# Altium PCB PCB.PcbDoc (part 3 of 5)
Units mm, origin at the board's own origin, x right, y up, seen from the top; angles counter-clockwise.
Board outline 101.6 x 53.34 mm, 6 copper layers (Top Layer, Int1 (GND), Int2, Int3, Int4 (GND), Bottom Layer), stack 1.625 mm thick; 228 components, 228 nets, 1016 pads, 995 vias.
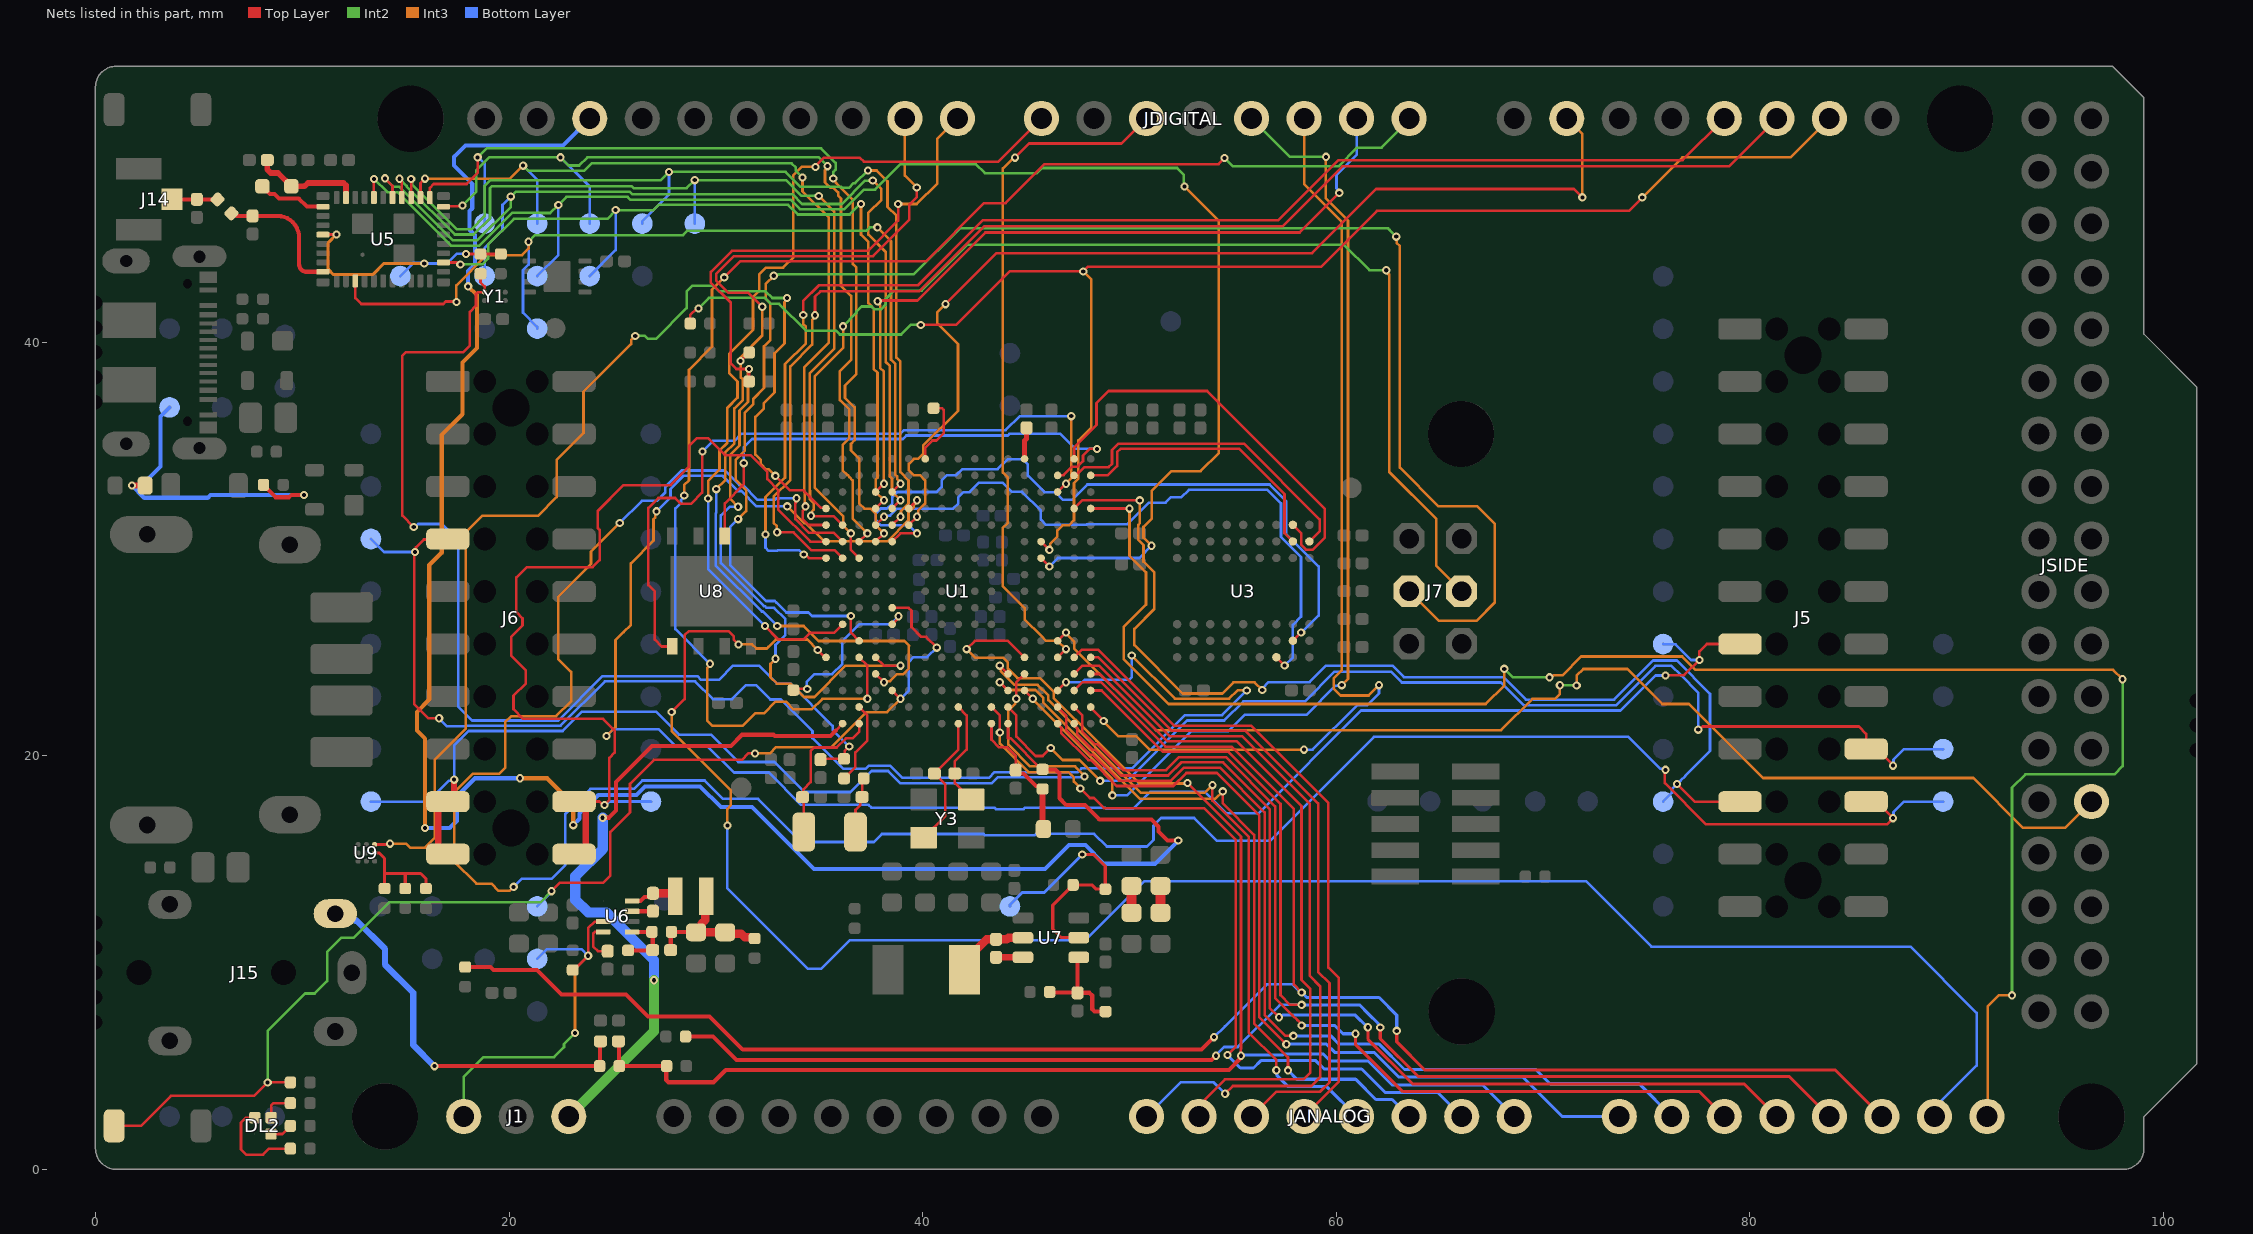
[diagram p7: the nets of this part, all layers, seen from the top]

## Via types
v1: diameter 0.4, hole 0.2, Top Layer to Bottom Layer, tented both sides, 995 vias

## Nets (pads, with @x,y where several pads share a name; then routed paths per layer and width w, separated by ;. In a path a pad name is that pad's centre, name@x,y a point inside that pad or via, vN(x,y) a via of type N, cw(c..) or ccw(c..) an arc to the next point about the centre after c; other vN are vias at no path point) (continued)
LEFT: JANALOG.22 R25.1 U1.T3 | length 97.2
  Top Layer w0.127: U1.T3@47.326,23.153 47.726,23.553 48.615,23.553 51.732,20.436 54.943,20.436 57.946,17.433 57.946,8.933 v1(58.326,8.553)
  Top Layer w0.15: v1(62.924,6.696) 62.924,6.163 64.291,4.796 84.142,4.796 JANALOG.22@86.386,2.553
  Top Layer w0.2: R25.1@17.878,9.784 19.103,9.784 19.243,9.644 21.343,9.644 22.528,8.459 25.653,8.459 26.722,7.39 29.697,7.39 31.297,5.79 53.49,5.79 v1(54.09,6.39)
  Bottom Layer w0.127: v1(54.09,6.39) 54.611,6.911 56.644,8.943 57.888,8.943 58.278,8.553 v1(58.326,8.553)
  Bottom Layer w0.15: v1(58.326,8.553) 58.575,8.305 62.075,8.305 62.924,7.455 v1(62.924,6.696)
M_7: C4.1 J15.2 R22.2 | length 19
  Top Layer w0.2: v1@16.389,4.989 24.371,4.989 R22.2@24.376,4.994 ; R22.2@24.38,4.99 24.4,5.01 24.4,6.17 C4.1@24.42,6.19
  Bottom Layer w0.3: J15.2@11.6,12.363 12.247,12.363 12.588,12.022 12.635,12.022 14,10.657 14,9.9 15.367,8.533 15.367,6.01 v1(16.389,4.988)
MEMS_32.768kHz: C72.1 R6.2 R9.1 Y1.2 | length 50.5
  Top Layer w0.127: v1(15.39,31.059) 14.843,31.606 14.843,39.348 14.999,39.505 17.763,39.505 18.1,39.841 18.1,41.461 18.4,41.761 18.4,42.318 18.497,42.415 Y1.2@18.819,42.415 18.819,42.692 18.619,42.892 R9.1@18.619,43.31 ; C72.1@35.065,19.805 35.104,19.844 35.646,19.844 35.649,19.847 36.097,19.847 36.225,19.975 36.225,20.225 v1(36.45,20.45)
  Bottom Layer w0.127: v1(15.39,31.059) 15.457,31.059 15.601,31.203 16.75,31.203 17.541,30.411 17.541,22.374 18.212,21.704 22.382,21.704 24.524,23.846 29.103,23.846 29.278,23.67 30.141,23.67 30.823,24.352 32.08,24.352 32.949,23.482 33.61,23.482 35.646,21.447 35.646,21.254 v1(36.45,20.45)
MIC: C4.2 JANALOG.16 R22.1 R23.2 U1.N5 | length 78.3
  Top Layer w0.127: v1(42.126,25.153) 42.53,25.557 44.122,25.557 U1.N5@44.922,24.757 ; v1(52.812,18.677) 55.394,16.095 55.394,5.824 55.382,5.812 55.382,5.497 v1(55.39,5.49)
  Top Layer w0.2: C4.2@25.29,6.19 25.31,6.17 25.31,5.01 R22.1@25.33,4.99 27.532,4.99 27.6,4.921 27.6,4.326 27.717,4.209 29.878,4.209 30.478,4.809 54.809,4.809 55.371,5.371 v1@55.371,5.471
  Top Layer w0.3: v1@55.371,5.471 v1(55.39,5.49)
  Int3 w0.127: v1(42.126,25.153) 42.536,24.743 43.888,24.743 44.117,24.515 44.117,24.21 44.574,23.753 45.679,23.753 46.332,23.099 46.332,22.795 48.403,20.724 50.474,18.653 52.788,18.653 v1(52.812,18.677)
  Bottom Layer w0.15: v1(55.39,5.49) 55.43,5.53 57.415,5.53 57.457,5.573 59.374,5.573 59.707,5.239 61.54,5.239 62.702,4.077 67.081,4.077 JANALOG.16@68.606,2.553
Net3V3_EN_X: 3V3_EN.X J1.1 R30.2 U6.3 | length 18.2
  Top Layer w0.127: R30.2@23.178,9.679 v1(23.825,10.326) 23.825,10.662 23.825,11.658 24.146,11.979 U6.3@24.621,11.979
  Int2 w0.127: J1.1@17.806,2.553 17.806,4.457 18.772,5.423 22.172,5.423 22.655,5.906 22.655,6.054 v1(23.19,6.59)
  Int3 w0.127: v1(23.19,6.59) 23.19,9.691 v1(23.825,10.326)
  Bottom Layer w0.127: 3V3_EN.X@21.362,10.173 21.83,10.641 23.51,10.641 v1(23.825,10.326)
Net5V_EN_X: 5V_EN.X R35.2 R36.1 U7.2 | length 12.7
  Top Layer w0.15: U7.2@47.55,11.2 46.706,11.2 46.289,11.616 46.289,12.767 R36.1@47.275,13.753 48.181,13.753 48.387,13.547 R35.2@48.831,13.547 48.831,14.669 48.274,15.226 v1(47.718,15.226)
  Bottom Layer w0.15: 5V_EN.X@44.222,12.713 44.222,12.793 44.805,13.377 45.869,13.377 v1(47.718,15.226)
NetC20_1: C20.1 U7.6 | length 1.3
  Top Layer w0.3: C20.1@43.55,10.25 U7.6@44.85,10.25
NetC20_2: C20.2 L1.1 U7.5 | length 3.7
  Top Layer w0.4: L1.1@42.016,9.653 42.016,10.103 42.566,10.653 42.619,10.653 43.086,11.12 44.069,11.12 44.149,11.2 U7.5@44.85,11.2
NetC35_2: C35.2 U1.N17 | length 1.5
  Top Layer w0.25: U1.N17@44.926,34.353 44.926,35.227 45.026,35.327 C35.2@45.026,35.853
NetC36_2: C36.2 L4.2 R7.2 U1.L1 | length 6.6
  Top Layer w0.127: U1.L1@43.326,21.553 43.326,20.778 43.698,20.407 44.093,20.407 44.5,20 C36.2@44.5,19.3 ; L4.2@45.778,16.454 L4.2@45.8,16.476
  Top Layer w0.2: C36.2@44.5,19.3 44.658,19.142 44.883,19.142 45.485,18.54 45.65,18.54 R7.2@45.8,18.39
  Top Layer w0.3: L4.2@45.8,16.476 R7.2@45.8,18.39
NetC38_1: C38.1 R14.1 U5.41 | length 6.6
  Top Layer w0.2: R14.1@6.572,46.228 ccw(c6.881,46.538) 6.881,46.1 C38.1@7.6,46.1 8.807,46.1 cw(c8.807,45.06) 9.847,45.06 9.847,43.76 ccw(c10.207,43.76) 10.207,43.4 U5.41@11,43.4
NetC39_1: C39.1 J14.SIG R14.2 | length 2.2
  Top Layer w0.2: J14.SIG@3.731,46.932 ccw(c3.731,46.904) J14.SIG@3.703,46.904 C39.1@4.903,46.904 5.102,46.906 ccw(c5.129,47.104) 5.128,46.904 5.896,46.904 R14.2@5.9,46.9
NetC42_1: C42.1 L2.2 U5.31 | length 5.3
  Top Layer w0.28: C42.1@8.308,48.804 8.308,48.347 8.475,48.18 8.827,48.18 L2.2@9.475,47.532 10.107,47.532 10.271,47.696 11.999,47.696 12.115,47.58 U5.31@12.115,46.99
NetC43_1: C43.1 L3.1 U6.8 | length 2.3
  Top Layer w0.2: U6.8@25.871,12.979 26.359,12.979 26.547,13.168 26.726,13.168 C43.1@26.907,13.349
  Top Layer w0.4: C43.1@26.907,13.349 27.84,13.349 L3.1@27.988,13.201
NetC43_2: C43.2 U6.7 | length 1
  Top Layer w0.2: U6.7@25.871,12.479 C43.2@26.907,12.479
NetC47_1: C47.1 R15.1 R16.2 U6.5 | length 3.1
  Top Layer w0.2: R16.2@25.758,10.586 26.934,10.586 C47.1@26.947,10.599 26.947,11.439 R15.1@26.907,11.479 U6.5@25.871,11.479
NetC47_2: C47.2 C48.2 C49.2 L3.2 R15.2 R39.1 | length 7
  Top Layer w0.2: C47.2@27.817,10.599 27.817,11.439 R15.2@27.857,11.479 29.028,11.479 C49.2@29.045,11.462
  Top Layer w0.4: C49.2@29.045,11.462 C49.2@29.083,11.462 ; L3.2@29.488,13.201 29.488,12.053 29.317,11.882 29.317,11.695 C49.2@29.083,11.462 ; R39.1@31.874,11.162 31.819,11.217 31.399,11.217 31.222,11.394 30.519,11.394 C48.2@30.451,11.462 C49.2@29.083,11.462
NetC50_2: C50.2 U6.4 | length 2
  Top Layer w0.127: U6.4@24.621,11.479 24.154,11.479 24.079,11.404 24.079,10.758 24.292,10.546 C50.2@24.768,10.546
NetC51_1: C51.1 R8.1 Y2.2 | length 2.8
  Top Layer w0.127: Y2.2@36.75,16.31 36.75,17.378 36.982,17.61 36.982,17.912 C51.1@37.07,18 37.07,18.82 R8.1@37.15,18.9
NetC52_1: C52.1 U1.J2 Y3.3 | length 5.2
  Top Layer w0.127: U1.J2@41.726,22.353 42.126,21.953 42.126,20.302 41.556,19.732 C52.1@41.556,19.143 41.556,18.679 Y3.3@42.35,17.885
NetC53_1: C53.1 U1.C1 Y2.1 | length 7.2
  Top Layer w0.127: C53.1@34.195,18 34.25,17.945 Y2.1@34.25,16.31 ; C53.1@34.23,18 34.23,18.366 34.584,18.72 34.584,20.227 34.755,20.397 35.845,20.397 36.288,20.841 36.612,20.841 36.926,21.155 U1.C1@36.926,21.553
NetC54_1: C54.1 U1.J1 Y3.1 | length 6.7
  Top Layer w0.127: Y3.1@40.05,16.035 41.1,17.085 41.1,18.604 C54.1@40.561,19.143 41.726,20.308 U1.J1@41.726,21.553
NetC60_1: C60.1 C61.2 | length 1.3
  Top Layer w0.5: C60.1@51.5,12.403 C61.2@51.5,13.703
NetC65_1: C65.1 R31.2 R33.2 U7.1 | length 5.2
  Top Layer w0.2: R31.2@46.155,8.588 R31.2@46.142,8.575 46.162,8.555 47.472,8.555 C65.1@47.492,8.535 ; U7.1@47.55,10.25 47.492,10.192 C65.1@47.492,8.535 ; R33.2@48.842,7.625 48.317,7.625 48.2,7.742 48.2,8.4 48.065,8.535 C65.1@47.492,8.535
NetC68_1: C68.1 C69.2 | length 1.3
  Top Layer w0.5: C68.1@50.1,12.403 C69.2@50.1,13.703
NetDL1_C: DL1.C PWR_LED.X R10.2 | length 16.3
  Top Layer w0.2: R10.2@8.125,33.085 8.71,32.5 9.362,32.5 9.472,32.61 v1(10.086,32.61)
  Top Layer w0.3: v1(1.767,33.062) DL1.C@2.4,33.062
  Bottom Layer w0.2: PWR_LED.X@3.582,36.843 3.146,36.407 3.146,33.98 2.227,33.062 v1(1.767,33.062) 2.355,32.473 5.431,32.473 5.569,32.61 v1(10.086,32.61)
NetDL2_1: DL2.1 R12.1 | length 1.1
  Top Layer w0.15: DL2.1@8.495,1.705 9.045,1.705 R12.1@9.425,2.085
NetDL2_2: DL2.2 R13.1 | length 1.6
  Top Layer w0.127: DL2.2@8.495,2.495 8.495,3.095 8.6,3.2 R13.1@9.425,3.2
NetDL2_3: DL2.3 R11.1 | length 4.7
  Top Layer w0.127: DL2.3@7.705,2.495 7.273,2.495 7.037,2.259 7.037,0.963 7.29,0.71 8.11,0.71 8.4,1 R11.1@9.425,1
NetJ1_3: J1.3 U1.B1 | length 33.1
  Top Layer w0.127: 35.799,21.22 35.799,21.225 U1.B1@36.122,21.549
  Top Layer w0.2: v1(24.525,17) 24.527,17.002 24.825,17.002 25.166,17.343 25.166,18.728 26.913,20.475 30.733,20.475 31.271,21.013 32.79,21.013 32.845,20.959 35.537,20.959 35.799,21.22
  Int2 w0.5: J1.3@22.886,2.553 27.009,6.676 v1(27.009,9.139)
  Bottom Layer w0.5: v1(24.525,17) 24.525,15.486 23.207,14.167 23.207,13.037 23.823,12.421 24.705,12.421 27.009,10.116 v1(27.009,9.139)
NetJDIGITAL_3: JDIGITAL.3 R7.1 U1.M1 | length 97.4
  Top Layer w0.127: U1.M1@44.126,21.553 44.126,20.851 44.239,20.851 R7.1@45.75,19.34
  Top Layer w0.2: R7.1@45.75,19.34 46.414,19.34 46.611,19.143 46.611,17.943 46.942,17.613 47.842,17.613 48.542,16.913 51.063,16.913 51.412,16.564 51.412,16.327 51.841,15.898 52.36,15.898 v1(52.362,15.897)
  Int3 w0.2: v1(15.932,16.5) 15.932,20.823 15.542,21.213 15.542,22.113 16.142,22.713 16.142,29.213 16.742,29.813 16.742,35.513 17.742,36.513 17.742,39.013 18.442,39.713 18.442,42.276 v1(18.021,42.696) ; v1(20.529,18.91) 21.844,18.91 23.101,17.653 v1(23.101,16.64)
  Bottom Layer w0.2: v1(15.932,16.5) 17.129,16.5 17.471,16.842 17.471,18.032 18.349,18.91 v1(20.529,18.91) ; v1(18.021,42.696) 18.021,43.432 18.349,43.76 18.349,45.177 18.095,45.432 18.095,46.346 18.221,46.473 18.221,47.648 17.334,48.535 17.334,48.961 17.886,49.513 22.602,49.513 JDIGITAL.3@23.902,50.813 ; v1(23.101,16.64) 23.41,16.949 23.41,17.202 24.315,18.107 26.162,18.107 26.568,18.513 29.242,18.513 30.242,17.513 31.742,17.513 34.742,14.513 45.913,14.513 47.077,15.677 47.871,15.677 48.775,14.773 51.238,14.773 v1(52.362,15.897)
NetL2_1: L2.1 U5.34 | length 3.3
  Top Layer w0.2: L2.1@8.075,47.532 8.447,47.16 8.652,47.16 8.867,46.946 9.827,46.946 10.222,46.55 U5.34@11,46.55
NetLPO_IN_X: LPO_IN.X R9.2 R40.2 U5.37 | length 12.8
  Top Layer w0.127: v1(17.922,44.265) 17.925,44.263 18.616,44.263 R9.2@18.619,44.26 R40.2@19.6,44.26
  Top Layer w0.15: U5.37@11,45.2 v1(11.65,45.2)
  Int3 w0.15: v1(11.65,45.2) 11.248,44.798 11.248,43.56 11.273,43.535 11.273,43.496 11.508,43.26 13.4,43.26 13.94,43.8 v1(15.9,43.8)
  Bottom Layer w0.127: LPO_IN.X@14.742,43.193 15.382,43.833 15.867,43.833 v1(15.9,43.8) 15.909,43.791 15.917,43.8 17,43.8 17.465,44.265 v1(17.922,44.265)
NetR3_2: R3.2 U1.E7 | length 7.9
  Top Layer w0.127: R3.2@33.776,23.146 33.858,23.229 v1(34.416,23.229) ; U1.E7@38.526,26.353 38.779,26.606 38.779,26.688 v1(38.831,26.741)
  Bottom Layer w0.127: v1(34.416,23.229) 34.399,23.245 34.399,23.578 34.764,23.943 35.617,23.943 36.117,24.444 36.117,25.544 36.926,26.353 38.444,26.353 v1(38.831,26.741)
NetR5_2: R5.2 U1.G17 | length 3.4
  Top Layer w0.127: U1.G17@40.126,34.353 40.126,34.905 40.464,35.243 40.669,35.243 41.011,35.586 41.011,36.726 40.935,36.803 R5.2@40.526,36.803
NetR6_1: R6.1 R8.2 U1.C2 | length 4.1
  Top Layer w0.127: R8.2@36.2,18.9 36.748,19.448 36.748,20.158 37.326,20.737 37.326,21.953 U1.C2@36.926,22.353
NetR32_2: R32.2 R34.2 R37.2 U9.C2 | length 5.4
  Top Layer w0.15: U9.C2@13.5,15.3 13.507,15.293 13.725,15.293 13.98,15.038 13.98,14.307 ; R37.2@13.98,13.575 13.98,14.307 ; R34.2@14.98,13.575 14.98,14.307 ; R32.2@15.98,13.575 15.98,14.051 15.724,14.307 14.98,14.307 ; 13.98,14.307 14.98,14.307
PA0_C: JANALOG.20 U1.T1 | length 48.6
  Top Layer w0.127: U1.T1@47.326,21.553 47.326,21.494 47.472,21.348 47.472,21.296 47.472,21.046 48.224,20.294 48.343,20.294 49.595,19.043 51.873,19.043 52.505,19.674 54.527,19.674 56.793,17.408 56.793,7.786 v1(57.226,7.353)
  Top Layer w0.15: v1(61.527,6.866) 61.527,6.296 63.701,4.123 79.735,4.123 JANALOG.20@81.306,2.553
  Bottom Layer w0.15: v1(57.226,7.353) 57.294,7.353 57.396,7.455 60.924,7.455 61.513,6.866 v1(61.527,6.866)
PA1: J6.17 J6.19 POWER_EN.X U1.N4 | length 52.2
  Top Layer w0.127: v1(44.526,22.753) 44.526,23.553 U1.N4@44.922,23.949
  Top Layer w0.3: J6.19@17.042,15.239 16.926,15.239 16.574,15.591 16.574,17.427 16.926,17.779 17.342,17.779 17.342,18.839 v1(17.343,18.841)
  Int3 w0.127: v1(44.526,22.753) 44.474,22.701 44.474,22.511 44.141,22.178 44.141,20.537 45.195,19.482 47.368,19.482 47.831,19.02 v1(47.831,18.994)
  Bottom Layer w0.127: POWER_EN.X@13.322,17.779 16.072,17.779 17.09,18.796 17.299,18.796 v1(17.343,18.841) 17.343,20.499 18.04,21.196 22.593,21.196 23.524,22.127 27.108,22.127 28.22,21.015 29.763,21.015 31.085,19.692 32.83,19.692 34.278,18.245 36.512,18.245 37.528,19.26 38.329,19.26 38.915,18.674 43.346,18.674 43.625,18.953 47.79,18.953 v1(47.831,18.994)
PA1_C: JANALOG.19 U1.T2 | length 46.4
  Top Layer w0.127: U1.T2@47.326,22.353 47.726,21.953 47.726,21.151 48.329,20.548 48.448,20.548 49.7,19.297 51.768,19.297 52.399,19.928 54.673,19.928 57.047,17.554 57.047,8.28 57.883,7.443 57.888,7.443 58.117,7.215 58.117,7.21 58.326,7.001 v1(58.326,6.953)
  Top Layer w0.15: v1(60.926,6.553) 60.926,6.048 63.219,3.754 77.564,3.754 JANALOG.19@78.766,2.553
  Bottom Layer w0.15: v1(58.326,6.953) 59.929,6.953 60.329,6.553 v1(60.926,6.553)
PA2: JDIGITAL.15 U1.N3 | length 50.6
  Top Layer w0.127: U1.N3@44.926,23.153 v1(45.326,22.753)
  Int2 w0.127: JDIGITAL.15@55.906,50.813 57.759,48.96 v1(59.504,48.96)
  Int3 w0.127: v1(45.326,22.753) 45.326,22.723 49.173,18.876 v1(49.173,18.083) ; v1(59.504,48.96) 59.499,48.955 59.499,46.949 60.566,45.883 60.566,23.713 v1(60.266,23.413)
  Bottom Layer w0.127: v1(49.173,18.083) 49.891,18.083 53.004,21.196 54.792,21.196 55.574,21.978 58.553,21.978 59.966,23.39 60.243,23.39 v1(60.266,23.413)
PA3: JDIGITAL.16 U1.U2 | length 47.4
  Top Layer w0.127: U1.U2@48.126,22.353 48.126,22.328 48.751,21.703 v1(48.751,21.678)
  Int3 w0.127: v1(48.751,21.678) 48.751,21.652 49.457,20.946 50.316,20.946 50.969,20.293 v1(58.44,20.293) ; JDIGITAL.16@58.446,50.813 58.446,47.644 60.266,45.824 60.266,24.113 59.875,23.722 59.875,23.251 60.213,22.913 61.566,22.913 v1(62.066,23.413)
  Bottom Layer w0.127: v1(58.44,20.293) 58.849,20.293 60.992,22.437 61.486,22.437 62.066,23.017 v1(62.066,23.413)
PA4: JANALOG.21 R24.1 U1.U3 | length 81.4
  Top Layer w0.127: U1.U3@48.126,23.153 48.656,23.153 51.627,20.182 54.793,20.182 57.305,17.671 57.305,8.418 57.769,7.953 v1(58.326,7.953)
  Top Layer w0.15: v1(62.126,6.853) 62.126,6.32 63.957,4.488 81.91,4.488 JANALOG.21@83.846,2.553
  Top Layer w0.2: R24.1@28.535,6.419 29.868,6.419 30.997,5.29 53.966,5.29 v1@54.166,5.49
  Top Layer w0.3: v1@54.166,5.49 v1(54.19,5.49)
  Bottom Layer w0.127: v1(54.19,5.49) 54.19,5.531 54.574,5.915 55.236,5.915 57.274,7.953 v1(58.326,7.953)
  Bottom Layer w0.15: v1(58.326,7.953) 61.126,7.953 61.555,7.524 62.026,7.054 62.026,7.02 62.126,6.92 v1(62.126,6.853)
PA6: J6.7 PCLK.X U1.R3 | length 69.6
  Top Layer w0.127: v1(16.619,21.81) 16.095,21.81 15.413,22.492 15.413,29.813 15.502,29.902 15.502,30.079 15.876,30.452 J6.7@17.316,30.452 ; U1.R3@46.526,23.153 v1(46.926,23.553)
  Int3 w0.127: v1(50.11,24.842) 52.197,22.755 54.825,22.755 55.23,23.16 55.665,23.16 v1(55.672,23.153)
  Bottom Layer w0.127: PCLK.X@13.322,30.479 13.951,29.85 v1(15.45,29.85) ; v1(16.619,21.81) 16.619,21.808 17.007,21.42 17.904,21.42 17.934,21.45 22.487,21.45 24.629,23.592 28.997,23.592 29.854,22.735 30.789,22.735 31.463,23.409 31.945,23.409 32.634,22.72 33.151,22.72 34.675,21.196 34.675,20.851 36.152,19.374 37.251,19.374 37.396,19.519 38.429,19.519 39.021,18.928 43.198,18.928 43.477,19.207 47.492,19.207 47.669,19.385 50.115,19.385 52.688,21.958 54.477,21.958 v1(55.672,23.153) ; v1(46.926,23.553) 47.734,23.553 47.855,23.674 49.998,23.674 50.11,23.786 v1(50.11,24.842)
PA7: JDIGITAL.13 U1.R5 | length 33.5
  Top Layer w0.127: v1(44.461,48.919) 45.143,49.601 49.614,49.601 JDIGITAL.13@50.826,50.813 ; U1.R5@46.526,24.753 v1(46.926,25.153)
  Int3 w0.127: v1(44.461,48.919) 44.407,48.919 43.882,48.393 43.882,33.687 44.117,33.452 44.117,31.255 43.872,31.01 43.872,28.208 44.936,27.143 44.936,26.591 45.736,25.791 45.974,25.553 46.526,25.553 v1(46.926,25.153)
PA8: U1.E15 U5.3 UART7_RX.X | length 46.4
  Top Layer w0.127: U5.3@12.565,42.96 12.565,42.135 12.856,41.844 16.819,41.844 16.936,41.961 17.434,41.961 v1(17.453,41.943) ; U1.E15@38.526,32.753 v1(38.926,33.153)
  Int2 w0.127: v1(20.943,44.851) 21.265,45.173 28.415,45.173 28.63,45.388 37.284,45.388 37.444,45.548 v1(37.81,45.548)
  Int3 w0.127: v1(17.453,41.943) 17.453,42.749 18.907,44.204 20.63,44.204 20.943,44.516 v1(20.943,44.851) ; v1(37.81,45.548) 38.469,44.89 38.469,39.151 38.667,38.954 38.667,33.605 38.771,33.502 38.771,33.382 38.926,33.227 v1(38.926,33.153)
  Bottom Layer w0.127: v1(20.943,44.851) 20.943,43.751 20.671,43.479 20.671,41.427 21.362,40.737 UART7_RX.X@21.362,40.653
PA9: JDIGITAL.17 U1.D15 | length 38.1
  Top Layer w0.127: U1.D15@37.726,32.753 v1(38.126,33.153) ; v1(37.825,41.978) 37.856,42.009 39.742,42.009 43.033,45.3 58.227,45.3 v1(60.144,47.216)
  Int3 w0.127: v1(37.825,41.978) 37.825,41.904 37.944,41.785 37.944,38.751 38.126,38.568 v1(38.126,33.153)
  Bottom Layer w0.127: v1(60.144,47.216) 60.144,47.29 60.009,47.425 60.009,48.076 60.986,49.052 JDIGITAL.17@60.986,50.813
PA10: BLE_ON.X U1.D14 U5.14 | length 41.4
  Top Layer w0.127: U5.14@16.83,43.85 17.418,43.85 cw(c17.418,43.53) 17.483,43.843 cw(c17.418,43.53) v1(17.644,43.756) ; U1.D14@37.726,31.953 v1(38.126,32.353)
  Int2 w0.127: v1(17.644,43.756) 18.711,43.756 18.992,44.037 18.992,44.727 20.228,45.963 24.757,45.963 25.155,46.362 v1(25.155,46.386) 25.173,46.368 26.965,46.368 27.235,46.638 33.498,46.638 33.965,46.172 36.471,46.172 36.977,46.678 v1(37.016,46.678)
  Int3 w0.127: v1(37.016,46.678) 37.016,45.2 37.369,44.846 37.369,41.881 37.634,41.616 37.634,38.701 37.817,38.518 37.817,33.448 37.723,33.354 37.723,32.756 v1(38.126,32.353)
  Bottom Layer w0.127: BLE_ON.X@23.902,43.193 25.155,44.446 v1(25.155,46.386)
PA15: U1.A14 U9.C3 | length 55.1
  Top Layer w0.127: v1(32.878,33.532) 33.571,32.838 34.224,32.838 35.079,31.983 35.296,31.983 U1.A14@35.326,31.953
  Top Layer w0.15: U9.C3@13.5,15.7 14.194,15.7 v1(14.24,15.746)
  Int2 w0.127: v1(26.1,40.3) 26.566,40.3 26.707,40.159 27.099,40.159 28.583,41.644 28.583,42.436 28.877,42.729 29.871,42.729 30.142,42.458 32.408,42.458 32.733,42.133 v1(33.438,42.133)
  Int3 w0.127: v1(14.24,15.746) 15.024,15.746 15.217,15.553 15.933,15.553 16.4,16.02 16.4,19.8 17.9,21.3 17.9,30.8 18.7,31.6 21.4,31.6 22.3,32.5 22.3,34.3 23.6,35.6 23.6,37.6 25.9,39.9 25.9,40.1 v1(26.1,40.3) ; v1(32.878,33.532) 32.564,33.846 32.434,33.846 32.172,34.107 32.172,34.3 31.906,34.567 31.906,36.375 32.316,36.786 32.316,37.05 32.838,37.572 32.838,39.459 33.32,39.941 33.32,41.941 33.438,42.059 v1(33.438,42.133)
PB0: JANALOG.11 U1.U5 | length 32.1
  Top Layer w0.127: U1.U5@48.126,24.753 48.493,24.753 52.048,21.198 55.611,21.198 59.122,17.687 59.122,9.551 59.672,9 59.672,4.199 59.226,3.753 57.106,3.753 JANALOG.11@55.906,2.553
PB1: JANALOG.12 U1.T5 | length 31.6
  Top Layer w0.127: U1.T5@47.326,24.753 47.702,25.128 48.477,25.128 52.153,21.452 55.886,21.452 59.622,17.717 59.622,9.751 60.126,9.246 60.126,4.233 JANALOG.12@58.446,2.553
PB2: JSIDE.28 U1.R6 | length 57.8
  Top Layer w0.127: U1.R6@46.526,25.553 v1(46.926,25.953)
  Int2 w0.127: v1(70.812,23.408) 70.817,23.404 71.62,23.404 v1(71.625,23.399)
  Int3 w0.127: v1(46.926,25.953) 46.926,25.904 47.339,25.491 47.339,25.171 51.279,21.231 67.97,21.231 69.491,22.752 70.578,22.752 70.812,22.985 v1(70.812,23.408) ; v1(71.625,23.399) 71.625,23.868 71.95,24.193 74.076,24.193 75.77,22.499 77.055,22.499 80.635,18.919 90.805,18.919 93.215,16.509 95.25,16.509 JSIDE.28@96.52,17.779
PB3: J7.3 U1.C6 | length 80.8
  Top Layer w0.127: v1(36.526,26.753) 36.526,25.953 U1.C6@36.926,25.553
  Int2 w0.127: v1(32.802,43.208) 32.854,43.26 33.035,43.26 33.05,43.275 39.569,43.275 41.798,45.505 62.502,45.505 62.577,45.43 62.577,45.423 v1(62.9,45.1)
  Int3 w0.127: v1(31.076,31.438) 31.467,31.828 31.467,32.837 30.955,33.348 30.955,34.308 31.398,34.751 31.398,36.586 31.808,36.996 31.808,37.261 32.33,37.782 32.33,39.794 32.632,40.096 32.632,41.874 32.42,42.087 32.42,42.826 v1(32.802,43.208) ; v1(62.9,45.1) 62.918,45.082 62.918,44.8 63.072,44.646 63.072,33.936 64.954,32.054 66.827,32.054 67.664,31.216 67.664,27.396 66.797,26.529 64.949,26.529 J7.3@63.526,27.953
  Bottom Layer w0.127: v1(31.076,31.438) 30.69,31.052 30.69,29.224 32.433,27.482 32.846,27.482 32.921,27.407 32.924,27.407 33.407,26.924 34.48,26.924 34.651,26.753 v1(36.526,26.753)
PB4: JDIGITAL.11 U1.B7 | length 43.1
  Top Layer w0.127: v1(32.372,26.273) 33.017,25.628 34.247,25.628 34.563,25.943 35.717,25.943 U1.B7@36.126,26.353 ; v1@34.8,48.5 35.213,48.913 36.966,48.913 37.152,48.726 43.659,48.726 JDIGITAL.11@45.746,50.813
  Int3 w0.127: v1(29.626,32.438) 29.626,33.289 30.177,33.84 30.177,34.754 30.551,35.127 30.551,36.816 31.046,37.312 31.046,38.094 30.643,38.497 30.643,39.428 31.797,40.583 31.797,42.172 32.093,42.467 32.093,43.265 32.427,43.599 33.249,43.599 33.75,44.1 33.75,48.071 34.152,48.473 v1(34.822,48.473)
  Bottom Layer w0.127: v1(29.626,32.438) 29.626,29.018 v1(32.372,26.273)
PB5: JANALOG.23 U1.A5 | length 93.7
  Top Layer w0.127: v1(27.863,22.113) 28.495,22.745 28.495,25.828 28.692,26.025 30.608,26.025 30.871,25.762 30.871,25.601 v1(31.09,25.383) ; v1(34.926,25.113) 35.285,24.753 U1.A5@35.326,24.753
  Int3 w0.127: 27.863,21.913 27.863,21.19 30.719,18.333 30.719,17.595 30.559,17.434 v1(30.559,16.622) ; v1(31.09,25.383) 31.758,25.383 31.959,25.181 32.461,25.181 32.537,25.257 32.542,25.257 32.903,25.618 34.42,25.618 v1(34.926,25.113)
  Bottom Layer w0.127: v1(30.559,16.622) 30.559,13.587 34.455,9.691 35.094,9.691 36.487,11.084 47.881,11.084 50.727,13.931 72.083,13.931 75.244,10.77 87.764,10.77 90.969,7.565 90.969,5.021 88.926,2.978 JANALOG.23@88.926,2.553
PB7: JDIGITAL.18 U1.C5 | length 70.7
  Top Layer w0.127: v1(30.405,43.132) 31.176,43.903 40.157,43.903 42.973,46.72 44.013,46.72 45.9,48.606 54.306,48.606 v1(54.6,48.9) ; U1.C5@36.926,24.753 37.326,24.353 v1(37.326,22.753)
  Int2 w0.127: v1(54.6,48.9) 55,48.5 60.1,48.5 61,49.4 62.19,49.4 63.526,50.735 JDIGITAL.18@63.526,50.813
  Int3 w0.127: v1(28.468,32.583) 28.468,33.086 28.698,33.316 28.698,38.66 29.816,39.778 29.816,42.543 v1(30.405,43.132) ; v1(29.718,24.446) 29.718,24.372 29.592,24.245 29.592,21.688 29.823,21.456 31.304,21.456 31.9,22.052 32.325,22.052 32.886,22.614 33.386,22.614 33.756,22.243 34.636,22.243 35.146,22.753 v1(37.326,22.753)
  Bottom Layer w0.127: v1(28.468,32.583) 28.468,32.517 28.315,32.364 28.315,32.227 28.041,31.954 28.041,26.122 v1(29.718,24.446)
PB8: JDIGITAL.10 R29.1 U1.D5 | length 49.7
  Top Layer w0.127: R29.1@31.61,38.098 31.605,38.104 31.605,38.695 v1(31.6,38.7) 30.99,38.7 30.723,38.967 30.723,41.903 29.76,42.865 29.76,43.399 30.773,44.411 37.35,44.411 38.816,45.878 v1(38.816,46.678) ; U1.D5@37.726,24.753 38.126,24.353 v1(38.926,24.353)
  Int3 w0.127: v1(31.076,32.038) 30.701,32.413 30.701,34.559 31.144,35.002 31.144,36.691 31.554,37.102 31.554,38.654 v1(31.6,38.7) ; v1(32.885,24.689) 32.642,24.445 32.642,23.79 32.949,23.482 33.61,23.482 34.254,22.838 34.764,22.838 36.278,24.353 v1(38.926,24.353) ; v1(38.816,46.678) 39.709,46.678 40.709,47.678 40.709,49.84 JDIGITAL.10@41.682,50.813
  Bottom Layer w0.127: v1(31.076,32.038) 30.667,32.038 30.242,31.613 30.242,29.314 32.328,27.228 32.376,27.228 32.451,27.153 32.819,27.153 33.362,26.609 33.362,25.837 32.885,25.36 v1(32.885,24.689)
PB9: JDIGITAL.9 R28.1 U1.D4 | length 47
  Top Layer w0.127: v1(31.187,39.09) 31.202,39.09 R28.1@31.61,39.498 ; v1(32.242,41.713) 31.561,42.393 30.592,42.393 30.014,42.97 30.014,43.294 30.878,44.157 37.596,44.157 39.349,45.91 39.349,46.641 39.716,47.009 v1(39.716,47.478) ; U1.D4@37.726,23.953 v1(38.126,23.553)
  Int3 w0.127: v1(30.017,32.888) 30.447,33.318 30.447,34.664 30.89,35.107 30.89,36.796 31.3,37.207 31.3,38.199 31.21,38.29 31.21,39.275 32.242,40.307 v1(32.242,41.713) ; v1(32.972,26.273) 34.242,26.273 34.971,25.544 39.123,25.544 39.344,25.323 39.336,25.315 39.336,24.762 39.336,24.21 39.069,23.943 38.764,23.943 38.426,23.605 38.178,23.605 v1(38.126,23.553) ; JDIGITAL.9@39.142,50.813 39.142,48.052 v1(39.716,47.478)
  Bottom Layer w0.127: v1(30.017,32.888) 30.017,31.748 29.988,31.718 29.988,29.208 32.222,26.974 32.271,26.974 v1(32.972,26.273)
PB10: U1.P11 U5.28 WIFI_ON.X | length 74.9
  Top Layer w0.127: U5.28@13.465,46.99 v1(13.465,47.89) ; U1.P11@45.726,29.553 v1(46.126,29.153)
  Int2 w0.127: v1(13.465,47.89) 13.479,47.89 14.113,47.256 14.602,47.256 17.194,44.664 18.565,44.664 20.15,46.249 21.613,46.249 21.62,46.242 21.991,46.242 v1(22.382,46.633) 22.772,47.023 25.727,47.023 25.858,46.892 33.604,46.892 34.07,46.426 36.212,46.426 37.154,47.368 37.695,47.368 38.94,48.613 42.566,48.613 43.006,48.173 45.526,48.173 45.771,48.418 52.302,48.418 52.628,48.092 52.628,47.559 v1(52.663,47.524)
  Int3 w0.127: v1(51.071,30.153) 50.681,30.543 50.681,31.062 51.071,31.453 51.071,32.8 52.028,33.757 53.436,33.757 54.324,34.645 54.324,45.863 v1(52.663,47.524)
  Bottom Layer w0.127: WIFI_ON.X@21.362,43.193 22.382,44.213 v1(22.382,46.633) ; v1(46.126,29.153) 46.536,29.562 50.481,29.562 v1(51.071,30.153)
PB11: JDIGITAL.25 R19.1 U1.P12 | length 76.1
  Top Layer w0.127: R19.1@28.76,40.898 28.76,41.308 29.082,41.63 v1(29.156,41.63) ; v1(39.91,40.83) 41.622,40.83 44.209,43.417 v1(47.767,43.417) 48.002,43.652 59.28,43.652 61.973,46.344 74.144,46.344 v1(74.8,47) ; U1.P12@45.726,30.353 v1(46.126,29.953)
  Int2 w0.127: v1(29.156,41.63) 29.665,42.139 32.368,42.139 32.661,41.846 33.055,41.846 34.351,40.55 35.81,40.55 35.994,40.367 38.958,40.367 39.422,40.83 v1(39.91,40.83)
  Int3 w0.127: v1(46.126,29.953) 46.178,30.005 46.178,30.253 46.517,30.591 46.517,30.896 46.764,31.143 47.069,31.143 47.317,31.391 47.317,33.188 47.528,33.399 47.528,35.245 48.154,35.871 48.154,43.031 v1(47.767,43.417) ; v1(74.8,47) 76.732,48.932 81.965,48.932 JDIGITAL.25@83.846,50.813
PB12: J5.19 PB12.X U1.T14 | length 52.5
  Top Layer w0.127: U1.T14@47.326,31.953 47.726,32.353 50.496,32.353 v1(50.501,32.348) ; v1(76.482,18.633) 77.336,17.779 J5.19@79.525,17.779
  Int3 w0.127: v1(50.501,32.348) 50.501,31.242 50.427,31.168 50.427,30.438 50.681,30.184 50.681,29.383 51.204,28.86 51.204,27.106 50.236,26.138 50.236,25.341 52.568,23.009 54.491,23.009 55.032,23.55 56.044,23.55 v1(56.422,23.173)
  Bottom Layer w0.127: v1(56.422,23.173) 56.422,23.247 56.735,23.56 58.704,23.56 59.501,24.357 62.712,24.357 63.271,23.798 68.081,23.798 69.165,22.713 73.435,22.713 75.323,24.602 76.466,24.602 78.074,22.993 78.074,20.226 76.879,19.03 76.879,19.027 76.651,18.798 76.647,18.798 v1(76.482,18.633) 76.236,18.388 76.236,18.21 PB12.X@75.805,17.779
PB13: JANALOG.24 U1.U14 | length 88.1
  Top Layer w0.127: U1.U14@48.126,31.953 49.996,31.953 v1(50.001,31.948)
  Int2 w0.127: v1(68.125,24.199) 68.537,23.787 v1(70.316,23.787) ; v1(92.677,8.41) 92.677,18.451 93.325,19.099 97.625,19.099 98.025,19.499 v1(98.025,23.699)
  Int3 w0.127: v1(50.001,31.948) 50.001,29.662 50.8,28.863 50.8,27.307 49.719,26.226 49.719,24.68 51.899,22.501 67.227,22.501 68.125,23.399 v1(68.125,24.199) ; v1(70.316,23.787) 70.39,23.787 70.492,23.89 70.929,23.89 71.838,24.799 76.725,24.799 77.371,24.153 97.571,24.153 v1(98.025,23.699) ; JANALOG.24@91.466,2.553 91.499,2.586 91.499,7.873 92.036,8.41 v1(92.677,8.41)
PC0: JANALOG.15 U1.L2 | length 38.8
  Top Layer w0.127: U1.L2@43.326,22.353 43.732,21.947 v1(43.732,21.126) ; v1(47.625,18.418) 48.089,17.954 48.278,17.954 48.77,17.462 53.601,17.462 55.14,15.924 55.14,5.929 v1(54.736,5.525)
  Int3 w0.127: v1(43.732,21.126) 43.732,20.587 45.111,19.208 47.05,19.208 47.311,18.946 47.311,18.753 47.625,18.439 v1(47.625,18.418)
  Bottom Layer w0.15: v1(54.736,5.525) 55.36,4.9 56.001,4.9 56.354,5.253 59.017,5.253 59.419,4.85 61.229,4.85 62.36,3.719 64.899,3.719 JANALOG.15@66.066,2.553
PC1: DFSDM1_DATIN0.X J5.18 U1.M2 | length 54.9
  Top Layer w0.127: U1.M2@44.126,22.353 44.526,21.953 44.526,20.923 45.466,19.983 45.805,19.983 v1(46.192,20.37) ; v1(77.504,21.26) 77.56,21.26 77.715,21.415 85.269,21.415 85.625,21.059 J5.18@85.625,20.319 ; J5.18@86.145,20.319 v1@86.925,19.539
  Int3 w0.127: v1(46.192,20.37) 46.768,19.794 47.584,19.794 48.583,18.794 v1(48.583,18.784)
  Bottom Layer w0.127: v1(48.583,18.784) 49.873,18.784 52.793,21.704 54.582,21.704 55.507,22.629 58.486,22.629 59.923,24.066 62.644,24.066 63.171,23.538 67.969,23.538 69.07,22.437 73.517,22.437 75.428,24.348 76.208,24.348 76.66,23.896 77.504,23.052 v1(77.504,21.26) ; v1(86.925,19.519) 86.946,19.54 86.946,19.819 87.446,20.319 DFSDM1_DATIN0.X@89.345,20.319 DFSDM1_DATIN0.X@89.327,20.3
PC2: JANALOG.14 U1.M3 | length 35.5
  Top Layer w0.127: v1(43.726,23.553) U1.M3@44.126,23.153 ; v1(54.512,18.277) 54.512,17.695 56.031,16.177 56.031,7.047 57.666,5.411 v1(57.666,4.784)
  Int3 w0.127: v1(43.726,23.553) 44.104,23.175 45.456,23.175 45.824,22.807 45.824,22.584 50.489,17.92 54.155,17.92 v1(54.512,18.277)
  Bottom Layer w0.15: v1(57.666,4.784) 58.097,4.353 60.937,4.353 61.914,3.376 62.702,3.376 JANALOG.14@63.526,2.553
PC2_C: JANALOG.17 U1.R1 | length 41.4
  Top Layer w0.127: U1.R1@46.526,21.553 46.526,21.543 46.697,21.372 46.697,21.103 48.013,19.786 48.133,19.786 49.384,18.535 52.118,18.535 52.749,19.166 54.235,19.166 56.285,17.116 56.285,7.345 v1(57.585,6.045)
  Bottom Layer w0.15: v1(57.585,6.045) 57.592,6.051 58.093,6.051 58.095,6.053 59.526,6.053 59.926,5.653 61.826,5.653 63.009,4.47 69.009,4.47 70.926,2.553 JANALOG.17@73.686,2.553
PC3: JANALOG.13 U1.M4 | length 33.8
  Top Layer w0.127: v1(43.726,24.353) U1.M4@44.126,23.953 ; v1(54.012,18.577) 54.012,17.836 55.777,16.071 55.777,6.602 57.104,5.275 v1(57.104,4.787)
  Int3 w0.127: v1(43.726,24.353) 43.771,24.308 43.771,24.1 44.442,23.429 45.562,23.429 46.078,22.912 46.078,22.689 50.563,18.205 53.64,18.205 v1(54.012,18.577)
  Bottom Layer w0.15: v1(57.104,4.787) 57.142,4.749 57.142,4.523 57.671,3.994 59.545,3.994 JANALOG.13@60.986,2.553
PC3_C: JANALOG.18 U1.R2 | length 44.6
  Top Layer w0.127: U1.R2@46.526,22.353 46.926,21.953 46.951,21.929 46.951,21.208 48.119,20.04 48.238,20.04 49.489,18.789 52.013,18.789 52.644,19.42 54.381,19.42 56.539,17.262 56.539,7.45 57.536,6.453 v1@57.915,6.453
  Bottom Layer w0.15: v1(57.926,6.453) 58.158,6.453 58.16,6.455 58.945,6.455 58.949,6.451 59.734,6.451 60.134,6.051 62.073,6.051 63.3,4.824 69.643,4.824 70.333,4.134 74.644,4.134 JANALOG.18@76.226,2.553
PC4: JANALOG.9 U1.T4 | length 37.4
  Top Layer w0.127: U1.T4@47.326,23.953 47.726,24.353 48.534,24.353 51.943,20.944 55.435,20.944 58.722,17.658 58.722,9.351 59.226,8.846 59.226,4.453 58.8,4.027 55,4.027 v1(54.626,3.653)
  Bottom Layer w0.127: JANALOG.9@50.826,2.553 52.476,4.203 54.076,4.203 v1(54.626,3.653)
PC5: JANALOG.10 U1.U4 | length 32.5
  Top Layer w0.127: U1.U4@48.126,23.953 48.575,23.953 51.838,20.69 55.189,20.69 58.322,17.558 58.322,9.151 58.745,8.728 58.745,4.671 58.418,4.345 54.618,4.345 53.667,3.393 53.667,2.854 JANALOG.10@53.366,2.553
PC6: I2S2_MCK.X J5.13 U1.F14 | length 91.5
  Top Layer w0.127: U1.F14@39.326,31.953 v1(39.726,32.353) ; v1(75.925,23.878) 75.943,23.896 76.823,23.896 v1(77.56,24.633) 77.56,25.036 77.923,25.399 J5.13@79.525,25.399
  Int3 w0.127: v1(24.715,20.95) 25.149,21.384 25.149,25.588 25.539,25.979 25.891,26.331 25.891,29.304 26.985,30.398 26.985,31.437 27.074,31.526 27.074,31.763 v1(27.126,31.816) ; v1(33.454,32.058) 34.275,31.237 34.37,31.237 35.244,30.362 38.288,30.362 39.317,31.391 39.317,31.75 39.571,32.004 39.571,32.124 39.726,32.279 v1(39.726,32.353)
  Bottom Layer w0.127: v1(24.715,20.95) 25.044,21.28 27.237,21.28 28.088,20.428 29.631,20.428 30.875,19.184 32.561,19.184 34.124,17.621 37.39,17.621 37.529,17.483 43.473,17.483 43.54,17.416 44.883,17.416 44.958,17.491 48.819,17.491 48.872,17.439 50.186,17.439 51.003,18.256 53.655,18.256 54.698,17.213 56.238,17.213 61.208,22.183 73.744,22.183 75.439,23.878 v1(75.925,23.878) ; v1(27.126,31.816) 27.807,32.496 27.807,32.898 28.446,33.537 30.325,33.537 31.065,32.797 31.235,32.797 31.975,32.058 v1(33.454,32.058) ; I2S2_MCK.X@75.805,25.399 75.816,25.388 76.405,25.388 77.166,24.627 77.554,24.627 v1(77.56,24.633)
PC7: JDIGITAL.20 U1.F13 | length 50.6
  Top Layer w0.127: U1.F13@39.326,31.153 v1(39.726,31.553) ; v1(41.105,41.837) 43.568,44.3 58.828,44.3 61.93,47.402 71.498,47.402 v1(71.9,47)
  Int3 w0.127: v1(39.726,31.553) 39.778,31.605 39.778,31.853 40.117,32.191 40.117,33.315 39.869,33.562 39.564,33.562 39.331,33.796 39.331,34.11 39.573,34.352 39.782,34.352 40.024,34.594 40.024,34.994 41.708,36.679 41.708,39.907 40.712,40.902 40.712,41.444 v1(41.105,41.837) ; JDIGITAL.20@71.146,50.813 71.9,50.058 v1(71.9,47)
PC8: SDIO_D0.X U1.E13 U5.24 | length 48.4
  Top Layer w0.127: U5.24@15.265,46.99 v1(15.265,47.89) ; U1.E13@38.526,31.153 v1(38.926,31.553)
  Int2 w0.127: v1@15.26,47.885 15.304,47.84 15.304,47.631 17.48,45.455 18.184,45.455 18.822,46.093 18.822,47.55 19.104,47.833 27.341,47.833 27.741,48.233 33.365,48.233 34.08,47.518 36.046,47.518 36.105,47.459 36.428,47.459 36.657,47.688 36.739,47.688 37.347,48.295 v1(37.353,48.295)
  Int3 w0.127: v1(37.353,48.295) 37.773,48.295 38.298,47.771 38.298,46.544 38.723,46.118 38.723,39.257 38.921,39.059 38.921,33.711 39.317,33.315 39.317,32.191 38.951,31.826 38.951,31.578 v1(38.926,31.553)
  Bottom Layer w0.127: SDIO_D0.X@26.442,45.733 26.442,45.845 27.735,47.138 v1(27.735,48.227)
PC9: SDIO_D1.X U1.E14 U5.26 | length 49.4
  Top Layer w0.127: v1(14.002,47.918) 14.365,47.556 U5.26@14.365,46.99 ; U1.E14@38.526,31.953 v1(38.926,32.353)
  Int2 w0.127: v1(14.002,47.918) 14.411,47.51 14.708,47.51 17.299,44.918 18.459,44.918 20.082,46.54 v1(20.082,47.033) 20.326,47.277 25.832,47.277 25.954,47.155 33.7,47.155 34.175,46.68 36.091,46.68 37.221,47.81 v1(37.585,47.81)
  Int3 w0.127: v1(37.585,47.81) 37.6,47.81 38.003,47.406 38.003,46.883 37.378,46.258 37.378,45.197 38.215,44.36 38.215,39.046 38.413,38.849 38.413,33.5 38.517,33.396 38.517,32.762 v1(38.926,32.353)
  Bottom Layer w0.127: SDIO_D1.X@18.822,43.193 18.822,44.55 19.683,45.412 19.683,46.634 v1(20.082,47.033)
PC10: SDIO_D2.X U1.A13 U5.23 | length 42.1
  Top Layer w0.127: U5.23@15.715,46.99 15.715,47.684 v1(15.934,47.904) ; v1(34.34,32.058) 34.34,31.984 34.198,31.842 34.198,31.443 34.488,31.153 U1.A13@35.326,31.153
  Int2 w0.127: v1(20.682,48.533) 20.926,48.288 23.637,48.288 23.994,48.646 33.662,48.646 33.869,48.438 33.869,48.281 v1(34.191,47.959)
  Int3 w0.127: v1(15.934,47.904) 20.052,47.904 v1(20.682,48.533) ; v1(34.191,47.959) 34.191,47.289 35.465,46.014 35.465,39.977 34.278,38.79 34.278,32.738 34.3,32.716 34.3,32.098 v1@34.336,32.062
  Bottom Layer w0.127: v1(20.682,48.533) 21.362,47.853 SDIO_D2.X@21.362,45.733
PC11: SDIO_D3.X U1.B13 U5.25 | length 44.9
  Top Layer w0.127: v1(14.7,47.9) 14.7,47.826 14.815,47.711 U5.25@14.815,46.99 ; v1(34.6,31.6) 34.623,31.577 35.702,31.577 U1.B13@36.126,31.153
  Int2 w0.127: v1(14.7,47.9) 15.05,47.55 15.05,47.526 17.375,45.201 18.289,45.201 19.076,45.988 19.076,47.445 19.162,47.531 25.937,47.531 26.026,47.442 28.591,47.442 v1(28.982,47.833) 33.382,47.833 34.144,47.07 v1(34.976,47.07)
  Int3 w0.127: v1@34.607,31.607 34.652,31.652 34.652,31.818 34.73,31.897 34.73,32.22 34.554,32.397 34.554,32.821 34.532,32.844 34.532,38.487 35.719,39.675 35.719,46.325 34.976,47.068 v1(34.976,47.07)
  Bottom Layer w0.127: SDIO_D3.X@28.982,45.733 v1(28.982,47.833)
PC12: SDIO_CLK.X U1.C12 U5.20 | length 44.5
  Top Layer w0.127: U5.20@16.83,46.55 16.856,46.576 17.721,46.576 v1(17.747,46.602) ; U1.C12@36.926,30.353 v1(37.326,30.753)
  Int2 w0.127: v1(17.747,46.602) 18.416,47.271 18.416,48.315 19.034,48.933 v1(22.482,48.933) 22.872,48.542 23.391,48.542 23.782,48.933 34.979,48.933 v1(35.402,48.509)
  Int3 w0.127: v1(35.402,48.509) 35.402,48.435 35.279,48.312 35.279,47.717 35.535,47.461 35.688,47.461 35.917,47.232 35.917,47.079 36.054,46.942 36.054,42.719 36.543,42.231 36.543,39.142 35.992,38.591 35.992,37.201 36.452,36.74 36.452,35.356 36.14,35.044 36.14,34.42 36.136,34.415 36.136,33.791 36.364,33.562 36.378,33.562 36.452,33.488 36.452,33.474 36.615,33.312 36.615,31.464 v1(37.326,30.753)
  Bottom Layer w0.127: v1(22.482,48.933) 23.902,47.513 SDIO_CLK.X@23.902,45.733
PC13: BOOT0/PC13.X PB2.1 R4.1 U1.E3 U1.E8 | length 60.6
  Top Layer w0.127: PB2.1@0.9,2.1 2.2,2.1 3.65,3.55 7.675,3.55 v1(8.325,4.2) R4.1@9.425,4.2 ; v1(22.05,13.45) 22.464,13.864 24.555,13.864 24.901,14.21 24.901,16.308 25.848,17.255 25.848,18.64 27.008,19.8 31.252,19.8 31.563,20.111 v1(31.893,20.111) ; U1.E3@38.526,23.153 v1(38.926,22.753) ; U1.E8@38.526,27.153 39.326,27.153 39.462,27.017 39.462,26.217 39.932,25.747 40.161,25.747 v1(40.683,25.226)
  Int2 w0.127: v1(8.325,4.2) 8.325,6.686 10.139,8.5 10.6,8.5 11.2,9.1 11.2,10.5 11.9,11.2 12.494,11.2 14.203,12.909 21.509,12.909 v1(22.05,13.45)
  Int3 w0.127: v1(31.893,20.111) 32.611,20.111 32.913,20.413 35.584,20.413 37.28,22.108 38.282,22.108 v1(38.926,22.753)
  Bottom Layer w0.127: BOOT0/PC13.X@21.362,12.713 22.05,13.401 v1(22.05,13.45) ; v1(38.926,22.753) 39.336,23.162 39.336,24.541 39.558,24.762 40.22,24.762 v1(40.683,25.226)
PD0_5: U1.D13 U3.C9 | length 31.8
  Top Layer w0.127: U1.D13@37.726,31.153 v1(38.126,31.553) ; U3.C9@57.104,24.76 v1(57.504,24.36)
  Bottom Layer w0.127: v1(38.126,31.553) 38.178,31.605 38.426,31.605 38.764,31.943 41.469,31.943 41.726,32.201 41.726,32.505 41.969,32.748 42.274,32.748 42.728,33.203 43.871,33.203 44.317,32.757 44.806,32.757 45.717,31.846 45.717,31.41 45.964,31.162 47.92,31.162 47.955,31.197 49.91,31.197 50.947,32.235 51.741,32.235 51.996,32.49 52.504,32.49 52.872,32.858 56.671,32.858 57.326,32.203 57.326,30.574 58.294,29.606 58.294,28.832 ; v1(57.504,24.36) 57.9,24.756 57.9,26.332 58.293,26.725 58.293,28.832
PD1_5: U1.E12 U3.B8 | length 34.9
  Top Layer w0.127: U1.E12@38.526,30.353 38.926,30.753 v1(39.726,30.753) ; U3.B8@57.904,25.56 v1(58.304,25.96)
  Bottom Layer w0.127: v1(39.726,30.753) 39.336,31.143 37.983,31.143 37.736,31.391 37.736,31.715 37.974,31.953 38.278,31.953 38.531,32.205 38.531,32.51 38.772,32.751 40.676,32.751 40.92,32.995 40.92,33.299 41.183,33.562 41.624,33.562 41.919,33.857 43.629,33.857 44.116,34.343 44.817,34.343 45.086,34.075 45.086,33.543 45.886,32.743 46.424,32.743 46.797,32.371 47.218,32.371 47.96,33.113 52.368,33.113 ; 52.368,33.112 56.776,33.112 57.58,32.308 57.58,30.721 59.15,29.151 59.15,26.782 58.328,25.96 v1(58.304,25.96)
PD2: SDIO_CMD.X U1.D12 U5.22 | length 45.3
  Top Layer w0.127: U5.22@16.165,46.99 16.165,47.454 16.356,47.645 17.945,47.645 18.482,48.182 v1(18.482,48.933) ; U1.D12@37.726,30.353 v1(38.126,30.753)
  Int2 w0.127: v1(18.482,48.933) 18.918,49.369 35.095,49.369 35.793,48.671 35.793,48.347 35.677,48.232 v1(35.677,47.916)
  Int3 w0.127: v1(35.677,47.916) 35.677,47.842 35.81,47.709 35.81,47.698 36.625,46.882 36.625,43.774 36.797,43.602 36.797,38.451 36.246,37.9 36.246,37.306 36.714,36.838 36.714,35.258 36.536,35.08 36.536,34.757 36.926,34.366 36.926,32.201 37.179,31.948 37.483,31.948 37.736,31.696 37.736,31.143 v1(38.126,30.753)
  Bottom Layer w0.127: v1(18.482,48.933) 18.52,48.933 18.822,48.631 SDIO_CMD.X@18.822,45.733
PD3: DFSDM1_CKOUT.X J5.20 U1.B12 | length 121.7
  Top Layer w0.127: v1(33.901,32.448) 33.848,32.396 33.848,32.203 33.845,32.199 33.845,31.437 34.504,30.777 35.702,30.777 U1.B12@36.126,30.353 ; v1(75.925,19.316) 75.888,19.279 75.888,18.674 77.883,16.679 86.625,16.679 v1(86.925,16.979) ; J5.20@86.145,17.779 v1@86.925,16.999
  Int3 w0.127: v1(20.22,13.659) 20.207,13.659 20.009,13.461 19.488,13.461 19.14,13.809 18.419,13.809 17.348,14.88 17.348,18.224 18.243,19.119 19.518,19.119 19.812,19.413 19.812,21.618 20.106,21.913 22.279,21.913 22.998,22.631 22.998,24.053 22.377,24.674 22.377,27.683 23.965,29.271 23.965,29.865 v1(25.35,31.25)
  Bottom Layer w0.127: v1(20.22,13.659) 20.614,14.053 22.067,14.053 22.711,14.696 22.711,17.169 23.94,18.398 26.042,18.398 26.448,18.803 29.46,18.803 30.349,17.914 32.035,17.914 34.125,15.824 37.641,15.824 38.03,16.213 42.947,16.213 43.014,16.146 45.409,16.146 45.484,16.221 48.293,16.221 48.905,15.61 50.842,15.61 51.164,15.931 51.164,16.37 51.164,16.494 51.164,16.62 51.529,16.986 51.655,16.986 53.129,16.986 54.228,15.886 56.787,15.886 61.814,20.913 74.127,20.913 75.675,19.364 75.877,19.364 v1(75.925,19.316) ; v1(25.35,31.25) 26.428,32.328 27.148,32.328 27.553,32.733 27.553,33.003 28.341,33.791 30.43,33.791 31.14,33.082 31.31,33.082 32.019,32.372 32.859,32.372 32.935,32.448 v1(33.901,32.448) ; v1(86.925,16.979) 86.946,17 86.946,17.279 87.446,17.779 DFSDM1_CKOUT.X@89.345,17.779
PD4: J6.18 J6.20 PWDN.X U1.A12 | length 46
  Top Layer w0.127: J6.18@23.358,17.779 23.367,17.788 24.369,17.788 24.54,17.617 v1(24.614,17.617) 24.847,17.85 24.847,19.899 25.105,20.157 25.105,21.222 24.544,21.783 20.683,21.783 20.217,22.25 20.217,22.902 20.809,23.495 20.809,24.13 20.1,24.839 20.1,25.744 20.651,26.294 20.651,26.642 20.354,26.938 20.354,28.615 20.86,29.121 24.046,29.121 24.383,29.458 24.383,30.918 24.288,31.013 24.288,31.839 25.53,33.081 27.805,33.081 28.704,33.981 28.704,34.98 29.082,35.358 29.616,35.358 30.437,34.537 31.665,34.537 32.487,33.715 32.487,33.37 33.013,32.845 33.013,31.909 34.569,30.353 U1.A12@35.326,30.353
  Top Layer w0.3: J6.20@23.142,15.239 23.358,15.239 23.71,15.591 23.71,17.427 23.358,17.779 J6.18@23.142,17.779
  Bottom Layer w0.127: v1(24.614,17.617) 24.688,17.617 24.859,17.788 26.853,17.788 PWDN.X@26.862,17.779
PD5: JDIGITAL.23 U1.A11 | length 64.1
  Top Layer w0.127: v1(34.223,41.308) 34.223,41.982 34.99,42.749 39.764,42.749 42.914,45.9 57.2,45.9 60.102,48.802 76.755,48.802 JDIGITAL.23@78.766,50.813 ; v1(34.252,29.724) 34.326,29.724 34.498,29.553 U1.A11@35.326,29.553
  Int3 w0.127: v1(32.4,30.7) 32.4,32.502 33.346,33.448 33.346,38.935 34.355,39.944 34.355,40.747 34.223,40.879 v1(34.223,41.308)
  Bottom Layer w0.127: v1(32.4,30.7) 32.4,30.061 32.552,29.91 32.923,29.91 32.931,29.917 32.969,29.917 32.986,29.934 34.038,29.934 34.247,29.724 v1(34.252,29.724)
PD6: JDIGITAL.24 U1.B11 | length 66
  Top Layer w0.127: v1(32.965,30.803) 33.76,30.803 34.634,29.929 35.75,29.929 U1.B11@36.126,29.553 ; v1(34.794,41.296) 34.794,42.194 35.053,42.453 39.827,42.453 42.974,45.6 57.4,45.6 60.302,48.502 78.995,48.502 JDIGITAL.24@81.306,50.813
  Int3 w0.127: v1(32.965,30.803) 32.951,30.817 32.951,31.103 32.797,31.257 32.797,32.54 33.6,33.343 33.6,38.83 34.652,39.883 34.652,41.081 34.794,41.222 v1(34.794,41.296)
PD7: J7.4 U1.C11 | length 58.4
  Top Layer w0.127: v1(36.526,30.753) 36.526,29.953 U1.C11@36.926,29.553
  Int2 w0.127: v1(36.152,40.761) 36.787,41.396 36.787,41.46 37.049,41.721 37.529,41.721 37.663,41.587 37.986,41.587 38.215,41.816 38.215,42.088 38.618,42.491 39.946,42.491 42.154,44.699 60.381,44.699 61.602,43.478 v1(62.416,43.478)
  Int3 w0.127: v1(36.152,40.761) 36.152,39.723 34.786,38.357 34.786,32.949 36.166,31.569 36.166,31.114 v1(36.526,30.753) ; v1(62.416,43.478) 62.416,43.404 62.563,43.257 62.563,33.726 64.842,31.447 64.842,29.177 J7.4@66.066,27.953
PD8_5: U1.U16 U3.B2 | length 13.7
  Top Layer w0.127: U1.U16@48.126,33.553 48.949,33.553 49.408,34.012 49.408,34.676 49.571,34.838 55.313,34.838 57.499,32.652 57.499,30.764 U3.B2@57.904,30.36
PD9_5: U1.T17 U3.B1 | length 20.8
  Top Layer w0.127: U1.T17@47.326,34.353 47.326,34.91 48.408,35.991 48.408,37.054 48.988,37.634 53.757,37.634 59.451,31.941 59.451,30.548 58.868,29.964 58.54,29.964 58.308,30.196 58.308,30.755 U3.B1@57.904,31.16
PD10_5: U1.T16 U3.A2 | length 15.7
  Top Layer w0.127: U1.T16@47.326,33.553 47.388,33.553 47.559,33.723 47.587,33.723 47.816,33.953 48.99,33.953 49.154,34.117 49.154,34.781 49.466,35.092 55.527,35.092 59.197,31.423 59.197,30.853 U3.A2@58.704,30.36
PD11_5: U1.R15 U8.5 | length 35.1
  Top Layer w0.127: U8.5@27.891,25.283 27.377,25.283 27.049,25.612 27.049,27.941 26.736,28.254 26.736,31.977 27.221,32.462 28.029,32.462 28.299,32.192 28.81,32.192 29.336,32.718 29.336,33.936 29.343,33.943 29.343,34.707 v1(29.349,34.713) ; U1.R15@46.526,32.753 v1(46.926,33.153)
  Int3 w0.127: v1(46.926,33.153) 46.926,33.157 47.189,33.419 v1(47.189,36.42)
  Bottom Layer w0.127: v1(29.349,34.713) 29.858,35.222 30.895,35.222 31.241,35.569 38.936,35.569 39.107,35.74 44.015,35.74 44.696,36.42 v1(47.189,36.42)
PD12_5: U1.R16 U8.2 | length 24.9
  Top Layer w0.127: U8.2@30.431,30.623 30.431,31.748 30.431,32.204 31.346,33.119 v1(31.346,34.147) ; U1.R16@46.526,33.553 46.542,33.569 46.811,33.569 47.22,33.977 47.482,33.977 47.751,34.246 47.751,34.509 48.076,34.834 v1(48.433,34.834)
  Bottom Layer w0.127: v1(31.346,34.147) 31.346,34.915 31.745,35.314 39.041,35.314 39.212,35.486 44.12,35.486 44.198,35.563 46.662,35.563 47.391,34.834 v1(48.433,34.834)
